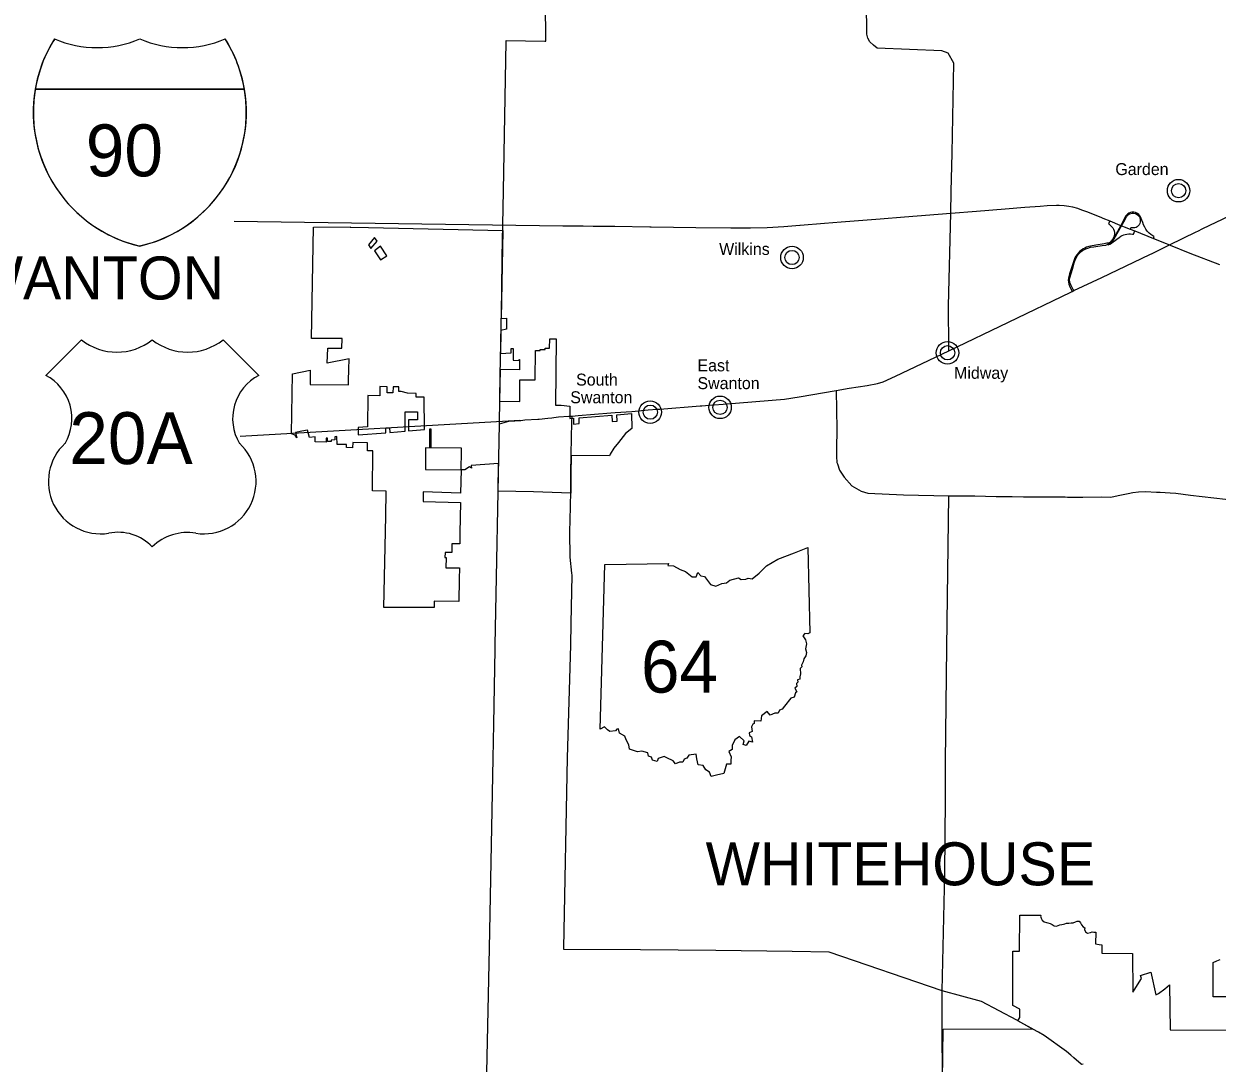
# Model space of a CAD drawing. Extents: x 0 to 750, y 0 to 507.
# Drawn here: x 76.6 to 180.7, y 149.3 to 239.9 of the extents above; entities that cross this region are included whole.
import ezdxf

# ---------------------------------------------------------------- set-up
doc = ezdxf.new("R2010")
doc.units = 0
for name, color, linetype in [('DV_X_Corp_Line', 7, 'Continuous'), ('GM_X_Corporation_Text', 7, 'Continuous'), ('GM_X_County', 7, 'Continuous'), ('GM_X_Interchange_Ramps', 7, 'Continuous'), ('GM_X_Interstate_Route', 7, 'Continuous'), ('GM_X_Rail_Line', 7, 'Continuous'), ('GM_X_State_Route', 7, 'Continuous'), ('GM_X_US_Route', 7, 'Continuous')]:
    doc.layers.add(name, color=color, linetype=linetype)

msp = doc.modelspace()

# ---------------------------------------------------------------- linework, layer by layer
at = {"layer": 'DV_X_Corp_Line'}
for points in [[(121.09, 199.12), (117.99, 199.2), (118.04, 201.61), (115.65, 201.42), (115.66, 201.21), (115.49, 201.3), (115.09, 201.05), (114.76, 201.04), (114.79, 202.69), (114.79, 202.73), (114.8, 202.94), (111.67, 202.98), (111.65, 201.08), (114.76, 201.04), (114.71, 199.02), (111.47, 199.14), (111.47, 198.7), (111.46, 198.28), (114.7, 198.19), (114.67, 195.57), (114.65, 194.59), (113.97, 194.59), (113.97, 193.84), (113.38, 193.85), (113.36, 193.4), (113.46, 193.39), (113.43, 192.49), (114.62, 192.49), (114.6, 191.51), (114.56, 189.58), (112.43, 189.61), (112.43, 189.03), (108.02, 189.03), (108.21, 197), (108.23, 199.18), (107.05, 199.21), (107.07, 202.7), (106.59, 202.7), (106.59, 203.42), (105.31, 203.43), (105.29, 202.97), (104.77, 202.99), (104.78, 203.25), (103.94, 203.27), (103.93, 203.95), (103.74, 203.93), (103.74, 203.66), (103.43, 203.63), (103.43, 203.52), (103.12, 203.52), (103.12, 203.82), (103, 203.82), (103, 203.47), (102.02, 203.48), (102.03, 203.92), (101.53, 203.88), (101.36, 204.5), (100.86, 204.42), (100.32, 204.32), (100.43, 203.84), (100.3, 204.08), (99.97, 204.2), (100.06, 209.43), (101.61, 209.74), (101.6, 208.49), (104.94, 208.46), (104.94, 208.84), (104.97, 209.79), (104.99, 210.73), (103.09, 210.36), (103.14, 211.67), (104.37, 211.67), (104.4, 212.52), (101.71, 212.52), (101.89, 222.22), (105.09, 222.25), (105.09, 222.23), (106.7, 222.2), (118.41, 221.92), (118.26, 214.26), (118.74, 214.27), (118.74, 213.31), (118.24, 213.19), (118.2, 211.21), (119.14, 211.25), (119.14, 211.62), (119.3, 211.63), (119.3, 210.61), (119.82, 210.6), (119.82, 210.68), (119.85, 210.68), (119.85, 209.78), (118.18, 209.8), (118.12, 207.05), (119.88, 207.02), (119.89, 208.9), (121.23, 208.91), (121.26, 211.45), (121.66, 211.45), (121.66, 211.54), (122.11, 211.54), (122.11, 211.67), (122.49, 211.67), (122.5, 212.47), (123.05, 212.48), (123.01, 206.7), (123.51, 206.69), (124.26, 206.61), (124.26, 205.53), (124.57, 205.56), (124.57, 205.03), (125.06, 205.08), (125.07, 205.6), (127.91, 205.83), (127.95, 205.26), (128.37, 205.29), (128.36, 205.86), (129.62, 205.96), (129.65, 204.65), (129.11, 204.23), (128.5, 203.43), (128.09, 202.94), (127.76, 202.42), (127.72, 202.27), (124.38, 202.31), (124.34, 200.7), (124.33, 199.02)], [(107.2, 221.33), (106.68, 220.68), (106.89, 220.36), (107.44, 220.99)], [(107.72, 220.57), (107.21, 220.16), (107.74, 219.38), (108.29, 219.73)], [(105.79, 204.1), (108.2, 204.29), (108.19, 204.68), (108.53, 204.71), (108.54, 204.32), (109.89, 204.43), (109.89, 206.11), (110.95, 206.11), (110.95, 205.42), (110.18, 205.42), (110.17, 204.45), (111.57, 204.56), (111.53, 207.38), (110.86, 207.39), (110.86, 207.71), (110.09, 207.74), (109.53, 207.87), (109.34, 207.89), (109.34, 208.29), (108.83, 208.29), (108.82, 207.77), (108.31, 207.77), (108.32, 208.3), (107.68, 208.32), (107.67, 207.52), (106.64, 207.54), (106.59, 204.81), (105.79, 204.73)], [(112.02, 204.59), (112.02, 203), (112.15, 203), (112.15, 204.6)]]:
    msp.add_lwpolyline(points, close=True, dxfattribs=at)
for points in [[(156.76, 147.7), (156.79, 150.08), (156.83, 152.25), (164.59, 152.3), (163.35, 153), (163.51, 153.28), (163.51, 154), (162.92, 154.34), (162.92, 159.08), (163.48, 159.07), (163.52, 162.2), (165.34, 162.2), (165.33, 162.12), (165.38, 161.94), (165.47, 161.77), (165.65, 161.64), (165.83, 161.57), (165.97, 161.55), (166.17, 161.47), (166.33, 161.39), (166.52, 161.29), (166.71, 161.25), (166.86, 161.32), (167.01, 161.37), (167.17, 161.39), (167.32, 161.42), (167.45, 161.45), (167.6, 161.5), (167.8, 161.51), (168, 161.53), (168.18, 161.55), (168.36, 161.62), (168.52, 161.67), (168.68, 161.67), (168.8, 161.53), (168.89, 161.37), (169.04, 161.2), (169.19, 161.11), (169.17, 160.95), (169.24, 160.76), (169.41, 160.65), (169.67, 160.71), (169.83, 160.74), (169.98, 160.73), (170.14, 160.73), (170.16, 160.73), (170.11, 159.7), (170.45, 159.64), (170.66, 159.62), (170.66, 158.89), (173.35, 158.87), (173.37, 155.5), (173.49, 155.68), (174.12, 156.68), (174.05, 156.95), (174.94, 157.23), (175.39, 155.27), (175.62, 155.38), (176.16, 155.78), (176.59, 156.14), (176.63, 152.2), (183.42, 152.18)], [(181.71, 155.09), (180.39, 155.09), (180.39, 158.09), (180.7, 158.22), (181, 158.34)]]:
    msp.add_lwpolyline(points, dxfattribs=at)
for centre, radius in [((177.37, 225.4), 0.982), ((177.37, 225.4), 0.623), ((143.64, 219.57), 0.982), ((143.64, 219.57), 0.623), ((157.21, 211.26), 0.982), ((157.21, 211.26), 0.623), ((137.36, 206.5), 0.982), ((131.27, 206.08), 0.982), ((131.27, 206.08), 0.623), ((137.36, 206.5), 0.623)]:
    msp.add_circle(centre, radius, dxfattribs=at)
at = {"layer": 'GM_X_County'}
msp.add_lwpolyline([(116.96, 145.78), (117.23, 159.32), (117.55, 175.88), (117.61, 178.91), (117.73, 185.39), (117.74, 185.73), (117.74, 185.76), (118.11, 205.05), (118.18, 209.31), (118.23, 212.05), (118.24, 212.53), (118.25, 213.36), (118.29, 215.25), (118.31, 216.41), (118.33, 217.57), (118.35, 218.73), (118.36, 219.62), (118.41, 222.41), (118.47, 225.4), (118.47, 225.43), (118.7, 238.38), (118.7, 238.49), (122.06, 238.43), (122.16, 238.43), (122.06, 248.84)], dxfattribs=at)
at = {"layer": 'GM_X_Interchange_Ramps'}
for points in [[(175.18, 221.23), (175.25, 221.4), (175.13, 221.46), (174.95, 221.58), (174.8, 221.69), (174.64, 221.86), (174.51, 222.05), (174.41, 222.23), (174.32, 222.42), (174.25, 222.62), (174.16, 222.84), (174.08, 223.06), (174, 223.2), (173.89, 223.33), (173.77, 223.42), (173.61, 223.49), (173.47, 223.52), (173.3, 223.53), (173.16, 223.5), (173.04, 223.44), (172.93, 223.37), (172.85, 223.3), (172.77, 223.2), (172.51, 222.71), (172.33, 222.37), (172.03, 221.83), (171.75, 221.32), (171.63, 221.14), (171.56, 221.06), (171.49, 220.99), (171.36, 220.89), (171.23, 220.83), (171.11, 220.81), (170.89, 220.77), (170.69, 220.73), (170.33, 220.67), (169.84, 220.59), (169.54, 220.53), (169.34, 220.47), (169.19, 220.4), (169.04, 220.33), (168.89, 220.22), (168.75, 220.11), (168.63, 219.98), (168.52, 219.84), (168.41, 219.69), (168.33, 219.54), (168.27, 219.38), (168.02, 218.67), (167.86, 218.16), (167.76, 217.78), (167.74, 217.57), (167.75, 217.45), (167.79, 217.25), (167.85, 217.11), (168.03, 216.71), (168.08, 216.61)], [(168.23, 216.68), (168.18, 216.79), (167.98, 217.2), (167.92, 217.33), (167.88, 217.44), (167.85, 217.53), (167.85, 217.65), (167.88, 217.81), (168.11, 218.55), (168.27, 219.12), (168.38, 219.42), (168.46, 219.58), (168.55, 219.74), (168.65, 219.87), (168.76, 219.99), (168.87, 220.09), (168.98, 220.18), (169.11, 220.25), (169.27, 220.32), (169.46, 220.4), (169.69, 220.46), (169.98, 220.51), (170.69, 220.61), (171.02, 220.66), (171.22, 220.72), (171.36, 220.78), (171.49, 220.87), (171.63, 221.02), (171.76, 221.21), (172.39, 222.34), (172.67, 222.84), (172.82, 223.11), (172.9, 223.23), (172.99, 223.31), (173.09, 223.38), (173.2, 223.42), (173.31, 223.44), (173.43, 223.43), (173.58, 223.41), (173.7, 223.36), (173.79, 223.3), (173.87, 223.22), (173.95, 223.12), (174, 223.01), (174.02, 222.9), (174.03, 222.77), (174.02, 222.64), (173.98, 222.53), (173.92, 222.43), (173.86, 222.35), (173.76, 222.26), (173.66, 222.2), (173.54, 222.17), (173.42, 222.15), (173.29, 222.15), (173.2, 222.17), (173.15, 222.05)], [(171.22, 220.72), (171.23, 220.69), (171.36, 220.74), (171.51, 220.82), (171.67, 220.94), (172.17, 221.33), (172.33, 221.43), (172.45, 221.5), (172.58, 221.55), (172.71, 221.59), (172.85, 221.61), (173.02, 221.63), (173.18, 221.64), (173.34, 221.62), (173.44, 221.6), (173.55, 221.89)], [(171.36, 222.77), (171.26, 222.51), (171.31, 222.47), (171.44, 222.37), (171.55, 222.26), (171.63, 222.16), (171.7, 222.03), (171.75, 221.9), (171.77, 221.75), (171.77, 221.6), (171.75, 221.48), (171.71, 221.37), (171.66, 221.27), (171.59, 221.15), (171.54, 221.08), (171.56, 221.06)]]:
    msp.add_lwpolyline(points, dxfattribs=at)
at = {"layer": 'GM_X_Interstate_Route'}
for points in [[(157.51, 223.43), (159.75, 223.61), (162.25, 223.81), (163.96, 223.95), (165.28, 224.05), (165.91, 224.1), (166.72, 224.14), (166.95, 224.14), (167.38, 224.11), (167.78, 224.05), (168.11, 223.98), (168.54, 223.86), (168.91, 223.74), (169.41, 223.55), (170.64, 223.06), (170.7, 223.03), (170.75, 223.01)], [(94.98, 222.73), (123.63, 222.34), (125.41, 222.32), (126.3, 222.31), (127.47, 222.29), (128.19, 222.29), (131.24, 222.25), (131.34, 222.25), (135.26, 222.2), (138.3, 222.17), (140.02, 222.16), (141.47, 222.19), (142.92, 222.28), (144.31, 222.39), (144.36, 222.4), (146.47, 222.56), (147.92, 222.67), (151.34, 222.94), (153.44, 223.11), (157.51, 223.43)], [(170.75, 223.01), (171.36, 222.77), (172.25, 222.4)], [(172.25, 222.4), (172.33, 222.37), (172.39, 222.34), (172.47, 222.31), (172.63, 222.25)], [(172.63, 222.25), (173.15, 222.05), (173.55, 221.89), (175.18, 221.23), (176.29, 220.78)], [(176.29, 220.78), (176.58, 220.67), (176.63, 220.65), (178.35, 219.96), (180.93, 218.96)]]:
    msp.add_lwpolyline(points, dxfattribs=at)
at = {"layer": 'GM_X_Rail_Line'}
for p, q in [((77.61, 234.26), (95.86, 234.26)), ((95.86, 234.26), (77.61, 234.26)), ((95.86, 234.26), (77.61, 234.26)), ((81.64, 212.4), (78.53, 209.29)), ((81.64, 212.4), (78.53, 209.29)), ((97.11, 209.29), (94, 212.4)), ((97.11, 209.29), (94, 212.4)), ((126.9, 178.42), (127.3, 192.78)), ((126.9, 178.42), (127.3, 192.78))]:
    msp.add_line(p, q, dxfattribs=at)
for points in [[(127.3, 192.78), (132.87, 192.88), (132.79, 192.7), (133.31, 192.67), (133.87, 192.36), (134.34, 192.17), (134.92, 191.71), (135.27, 191.71), (135.41, 192.09), (135.68, 191.8), (135.99, 191.75), (136.54, 191.06), (136.98, 190.91), (137.52, 191.15), (137.92, 191.19), (138.22, 191.42), (138.98, 191.62), (139.19, 191.5), (139.6, 191.52), (139.8, 191.61), (140.16, 191.53), (140.78, 192.05), (141.42, 192.67), (142.4, 193.25), (143.87, 193.8), (145.03, 194.29), (145.2, 186.84)], [(127.3, 192.78), (132.87, 192.88), (132.79, 192.7), (133.31, 192.67), (133.87, 192.36), (134.34, 192.17), (134.92, 191.71), (135.27, 191.71), (135.41, 192.09), (135.68, 191.8), (135.99, 191.75), (136.54, 191.06), (136.98, 190.91), (137.52, 191.15), (137.92, 191.19), (138.22, 191.42), (138.98, 191.62), (139.19, 191.5), (139.6, 191.52), (139.8, 191.61), (140.16, 191.53), (140.78, 192.05), (141.42, 192.67), (142.4, 193.25), (143.87, 193.8), (145.03, 194.29), (145.2, 186.84)], [(145.2, 186.84), (145.03, 186.74), (144.76, 186.79), (144.58, 186.58), (144.81, 186.23), (144.91, 185.86), (144.82, 185.45), (144.91, 185.12), (144.85, 184.84), (144.68, 184.56), (144.62, 184.29), (144.48, 184.01), (144.49, 183.86), (144.35, 183.73), (144.38, 183.26), (144.31, 183.01), (144.33, 182.78), (144.11, 182.73), (144.16, 182.54), (144.02, 182.4), (144.05, 182.15), (143.89, 182), (144.05, 181.69), (143.93, 181.59), (143.82, 181.21), (143.54, 181.13), (142.97, 180.43), (142.77, 180.17), (142.55, 180.1), (142.42, 179.83), (142.15, 179.83), (141.73, 179.65), (141.46, 179.97), (140.98, 179.58), (140.93, 179.13), (140.33, 179.15), (140.35, 178.92), (140.22, 178.86), (140.1, 178.63), (140.17, 178.23), (139.89, 178.12), (139.92, 177.89), (140.1, 177.75), (140.18, 177.3), (139.88, 177.39), (139.64, 177.01), (139.39, 177.1), (139.47, 177.42), (139.05, 177.8), (138.64, 177.5), (138.43, 177), (138.43, 176.67), (138.13, 176.47), (138.32, 176.01), (138.29, 175.69), (138.3, 175.38), (137.92, 175.39), (137.69, 174.57)], [(145.2, 186.84), (145.03, 186.74), (144.76, 186.79), (144.58, 186.58), (144.81, 186.23), (144.91, 185.86), (144.82, 185.45), (144.91, 185.12), (144.85, 184.84), (144.68, 184.56), (144.62, 184.29), (144.48, 184.01), (144.49, 183.86), (144.35, 183.73), (144.38, 183.26), (144.31, 183.01), (144.33, 182.78), (144.11, 182.73), (144.16, 182.54), (144.02, 182.4), (144.05, 182.15), (143.89, 182), (144.05, 181.69), (143.93, 181.59), (143.82, 181.21), (143.54, 181.13), (142.97, 180.43), (142.77, 180.17), (142.55, 180.1), (142.42, 179.83), (142.15, 179.83), (141.73, 179.65), (141.46, 179.97), (140.98, 179.58), (140.93, 179.13), (140.33, 179.15), (140.35, 178.92), (140.22, 178.86), (140.1, 178.63), (140.17, 178.23), (139.89, 178.12), (139.92, 177.89), (140.1, 177.75), (140.18, 177.3), (139.88, 177.39), (139.64, 177.01), (139.39, 177.1), (139.47, 177.42), (139.05, 177.8), (138.64, 177.5), (138.43, 177), (138.43, 176.67), (138.13, 176.47), (138.32, 176.01), (138.29, 175.69), (138.3, 175.38), (137.92, 175.39), (137.69, 174.57)], [(137.69, 174.57), (137.04, 174.41), (136.59, 174.31), (136.43, 174.69), (136.11, 174.89), (135.9, 175.26), (135.44, 175.31), (135.33, 175.83), (135.28, 176.25), (134.64, 176.15), (134.47, 175.89), (134.24, 175.82), (134.11, 175.56), (133.81, 175.54), (133.48, 175.42), (133.26, 175.67), (132.72, 175.93), (132.48, 176.06), (131.97, 175.86), (131.87, 175.61), (131.46, 175.72), (131.37, 175.99), (131.13, 176.07), (131.07, 176.36), (130.55, 176.51), (130.15, 176.45), (129.45, 176.68), (129.4, 177.06), (129.17, 177.51), (129.04, 177.83), (128.6, 178.08), (128.51, 178.46), (128.36, 178.44), (128.23, 178.29), (127.74, 178.22), (127.54, 178.37), (127.27, 178.64), (126.9, 178.42)], [(137.69, 174.57), (137.04, 174.41), (136.59, 174.31), (136.43, 174.69), (136.11, 174.89), (135.9, 175.26), (135.44, 175.31), (135.33, 175.83), (135.28, 176.25), (134.64, 176.15), (134.47, 175.89), (134.24, 175.82), (134.11, 175.56), (133.81, 175.54), (133.48, 175.42), (133.26, 175.67), (132.72, 175.93), (132.48, 176.06), (131.97, 175.86), (131.87, 175.61), (131.46, 175.72), (131.37, 175.99), (131.13, 176.07), (131.07, 176.36), (130.55, 176.51), (130.15, 176.45), (129.45, 176.68), (129.4, 177.06), (129.17, 177.51), (129.04, 177.83), (128.6, 178.08), (128.51, 178.46), (128.36, 178.44), (128.23, 178.29), (127.74, 178.22), (127.54, 178.37), (127.27, 178.64), (126.9, 178.42)]]:
    msp.add_lwpolyline(points, dxfattribs=at)
for centre, radius, start, end in [((89.43, 232.25), 11.99, 147.8216, 256.9941), ((88.68, 232.46), 11.22, 146.654, 170.759), ((83.01, 247.45), 9.57, 247.0848, 292.9105), ((83.01, 247.45), 9.57, 247.0848, 292.9105), ((84.04, 232.25), 11.99, 283.0065, 32.1787), ((90.46, 247.45), 9.57, 247.0916, 292.9084), ((90.46, 247.45), 9.57, 247.0916, 292.9084), ((84.04, 232.25), 11.99, 9.6475, 32.179), ((89.43, 232.25), 11.99, 170.3514, 256.9967), ((84.06, 232.25), 11.97, 282.7667, 9.6898), ((84.73, 216.32), 5, 231.813, 308.187), ((84.73, 216.32), 5, 231.813, 308.187), ((90.91, 216.32), 5, 231.813, 308.187), ((90.91, 216.32), 5, 231.813, 308.187), ((76.58, 205.53), 4.23, 329.1175, 62.6108), ((76.58, 205.53), 4.23, 329.1175, 62.6108), ((99.06, 205.53), 4.23, 117.3892, 210.8825), ((99.06, 205.53), 4.23, 117.3892, 210.8825), ((83.32, 200.03), 4.56, 133.0046, 278.7282), ((83.32, 200.03), 4.56, 133.0046, 278.7282), ((92.32, 200.03), 4.56, 261.2718, 46.9954), ((92.32, 200.03), 4.56, 261.2718, 46.9954), ((84.86, 191.52), 4.08, 43.4177, 101.8742), ((84.86, 191.52), 4.08, 43.4177, 101.8742), ((90.87, 191.25), 4.33, 79.9613, 134.7468), ((90.87, 191.25), 4.33, 79.9613, 134.7468)]:
    msp.add_arc(centre, radius, start, end, dxfattribs=at)
at = {"layer": 'GM_X_State_Route'}
for points in [[(150.75, 238.09), (150.44, 238.39), (150.26, 238.71), (150.18, 239.04), (150.17, 239.56), (150.08, 244.83), (150.01, 248.63), (149.82, 261.84), (149.83, 274.65), (149.57, 286.71)], [(157.31, 211.69), (157.28, 215.37), (157.51, 223.43), (157.54, 225.33), (157.61, 228.67), (157.77, 236.51), (157.25, 237.38), (156.71, 237.6), (151.08, 237.83), (150.75, 238.09)], [(178.89, 221.8), (179.06, 221.88), (179.49, 222.09), (182.98, 223.77), (184.15, 224.32), (185.38, 224.92), (185.96, 225.19), (186.2, 225.29)], [(176.28, 220.52), (176.58, 220.67), (178.89, 221.8)], [(170.67, 217.83), (174.85, 219.82)], [(174.85, 219.82), (175.05, 219.92), (176.28, 220.52)], [(167.97, 216.55), (168.08, 216.61), (168.23, 216.68), (170.67, 217.83)], [(157.31, 211.43), (162.52, 213.92), (167.97, 216.55)], [(147.49, 207.96), (148.62, 208.17), (150.19, 208.41), (151.09, 208.58), (151.6, 208.73), (152.67, 209.21), (157.31, 211.43)], [(157.31, 211.43), (157.31, 211.69)], [(124.38, 202.41), (124.44, 205.21)], [(124.44, 205.21), (124.45, 205.74)], [(124.35, 200.81), (124.38, 202.31), (124.38, 202.41)], [(124.33, 199.08), (124.34, 200.7), (124.35, 200.81)], [(124.32, 198.02), (124.33, 199.02), (124.33, 199.08)], [(124.43, 192.04), (124.27, 193.43), (124.26, 195.62), (124.32, 197.82), (124.32, 198.02)], [(156.73, 155.6), (156.96, 165.85), (157.02, 172.33), (157.04, 175.61), (157.16, 185.56), (157.33, 198.79)], [(123.73, 159.35), (124.04, 175.92), (124.34, 185.77), (124.37, 187.65), (124.45, 191.85), (124.43, 192.04)], [(156.73, 155.6), (146.88, 158.99), (143.66, 159.03), (136.98, 159.12), (130.43, 159.17), (123.72, 159.22), (123.73, 159.35)], [(163.87, 152.71), (163.25, 153.06), (160.17, 154.68), (156.73, 155.6)], [(156.74, 152.39), (156.73, 155.6)], [(156.76, 147.97), (156.74, 152.39)], [(165.15, 151.99), (165.04, 152.05), (164.24, 152.5), (163.87, 152.71)], [(169.03, 149.2), (168.9, 149.19), (168.87, 149.21), (168.24, 149.76), (167.96, 150), (167.58, 150.33), (165.63, 151.72), (165.15, 151.99)]]:
    msp.add_lwpolyline(points, dxfattribs=at)
at = {"layer": 'GM_X_US_Route'}
for points in [[(136.71, 206.71), (136.84, 206.72), (137.64, 206.78), (142.99, 207.22), (144.26, 207.42), (147.49, 207.96)], [(147.49, 207.96), (147.54, 204.59), (147.52, 202.88), (147.51, 202.22), (147.56, 201.7), (147.6, 201.57), (147.79, 201.01), (148.18, 200.41), (148.87, 199.66), (149.66, 199.18), (150.26, 199.03), (153.38, 198.88), (157.33, 198.79)], [(128.22, 206.04), (129.65, 206.15)], [(129.65, 206.15), (131.08, 206.27), (131.88, 206.33)], [(131.88, 206.33), (132.1, 206.34), (135.63, 206.63)], [(135.63, 206.63), (135.78, 206.64), (136.71, 206.71)], [(118.11, 205.05), (118.93, 205.3), (119.45, 205.33), (119.9, 205.36), (95.48, 203.97)], [(119.93, 205.36), (119.97, 205.36), (120.33, 205.4), (121.45, 205.47), (121.57, 205.48), (122.32, 205.56)], [(122.32, 205.56), (122.67, 205.59), (122.85, 205.61)], [(122.85, 205.61), (123.27, 205.66), (124.16, 205.72), (124.18, 205.72)], [(124.18, 205.72), (124.45, 205.74)], [(124.45, 205.74), (124.45, 205.74), (124.97, 205.78)], [(124.97, 205.78), (127.83, 206.01)], [(127.83, 206.01), (128.22, 206.04)], [(162.85, 198.72), (163.83, 198.71), (163.87, 198.71), (164.1, 198.71), (165.69, 198.69), (165.74, 198.69), (165.96, 198.69), (167.42, 198.69), (167.46, 198.69), (167.68, 198.68), (168.88, 198.67), (169.01, 198.67), (170.62, 198.69), (171.46, 198.68), (172.11, 198.81), (172.97, 198.98), (173.39, 199.06), (173.86, 199.12), (174.47, 199.15), (175.44, 199.11)], [(175.44, 199.11), (175.45, 199.11), (175.77, 199.1), (176.64, 199.04), (177.14, 199.01), (178.41, 198.85), (181.46, 198.5), (183.89, 198.27), (187.24, 197.91), (189.72, 197.62), (191.88, 197.58), (197.22, 197.25), (201, 197.25), (208.74, 197.09), (217.09, 196.95)], [(157.33, 198.79), (157.46, 198.79), (159.32, 198.77), (159.35, 198.77), (159.59, 198.77), (161.45, 198.73), (161.49, 198.72), (161.71, 198.72), (162.72, 198.72), (162.85, 198.72)]]:
    msp.add_lwpolyline(points, dxfattribs=at)

# ---------------------------------------------------------------- texts
at = {"layer": 'DV_X_Corp_Line'}
for s, p in [('Garden', (171.85, 226.76)), ('Wilkins', (137.28, 219.79)), ('East', (135.39, 209.64)), ('South', (124.8, 208.4)), ('Midway', (157.78, 208.99)), ('Swanton', (135.39, 208.09)), ('Swanton', (124.29, 206.86))]:
    msp.add_text(s, height=1.042, rotation=0, dxfattribs=at).set_placement(p)
at = {"layer": 'GM_X_Corporation_Text'}
for s, p in [('SWANTON', (68.46, 215.91)), ('WHITEHOUSE', (136.1, 164.81))]:
    msp.add_text(s, height=3.75, rotation=0, dxfattribs=at).set_placement(p)
at = {"layer": 'GM_X_Rail_Line'}
for s, p in [('90', (82.02, 226.65)), ('20A', (80.58, 201.55)), ('64', (130.46, 181.62))]:
    msp.add_text(s, height=4.528, dxfattribs=at).set_placement(p)

doc.saveas('drawing.dxf')
